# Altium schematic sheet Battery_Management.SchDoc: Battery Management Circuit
size A4; DrawnBy: Satya Mehta; Organization: Team- Ashwathama; Address1: Colorado Boulder; Address2: Author- Satya Mehta; Address3: Self Checkout Shopping Cart; DocumentNumber: 1; Revision: 1.0; SheetNumber: 1; SheetTotal: 7
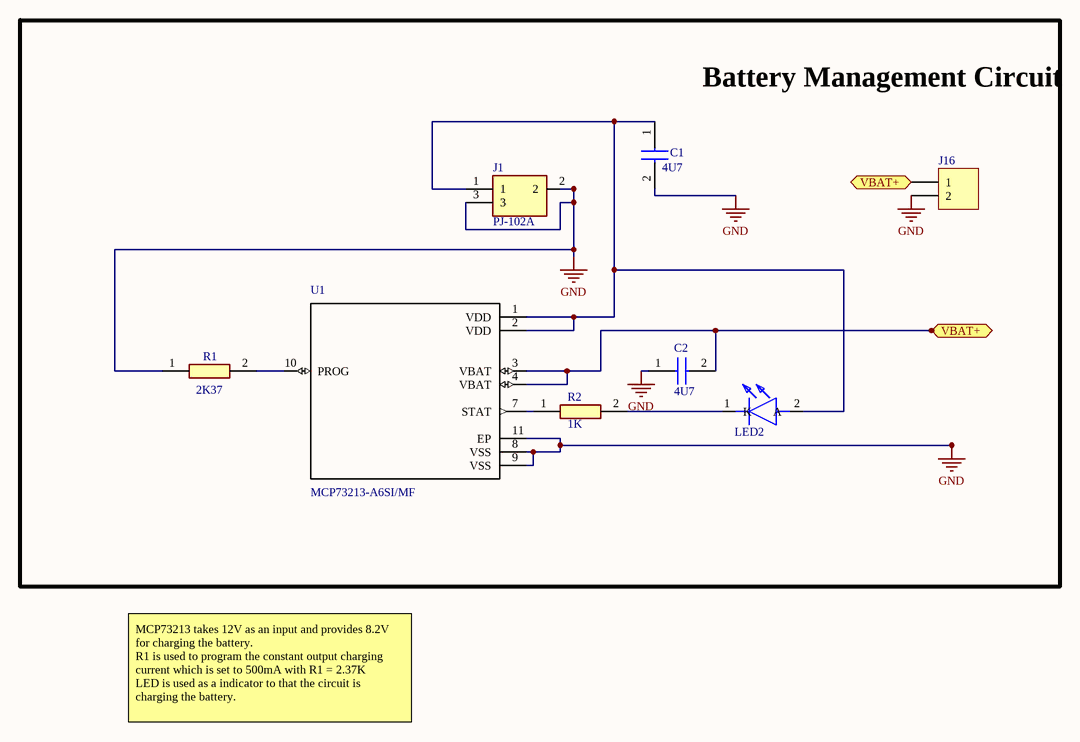
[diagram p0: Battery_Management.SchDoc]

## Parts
C1  value 4U7  [CAPC1608X90N]  (hidden comment: GRM188R61E475KE11D)
C2  value 4U7  [CAPC1608X90N]  (hidden comment: GRM188R61E475KE11D)
J1  PJ-102A  [PJ-102AH]
J16  Header 2  [HDR1X2]  (value not drawn)
LED2  SML-D12U1WT86  [LEDC1608X65N]  (value not drawn)
R1  value 2K37  [RESC1608X55N]  (hidden comment: ERJ-3EKF2371V)
R2  value 1K  [RESC1608X55N]  (hidden comment: RC0603FR-071KL)
U1  MCP73213-A6SI/MF  [*SON50P300X300X100-11N]

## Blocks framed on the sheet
Battery Management Circuit: C1 C2 J1 J16 LED2 R1 R2 U1

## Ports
VBAT+

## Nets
GND: C1.2 C2.1 J1.2 J1.3 J16.2 R1.1 U1.8(VSS) U1.9(VSS) U1.11(EP)
VBAT+: C2.2 J16.1 U1.3(VBAT) U1.4(VBAT) ; port VBAT+
NetC1_1: C1.1 J1.1 LED2.2(A) U1.1(VDD) U1.2(VDD)
NetLED2_1: LED2.1(K) R2.2
NetR1_2: R1.2 U1.10(PROG)
NetR2_1: R2.1 U1.7(STAT)

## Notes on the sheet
- MCP73213 takes 12V as an input and provides 8.2V for charging the battery.
  R1 is used to program the constant output charging current which is set to 500mA with R1 = 2.37K
  LED is used as a indicator to that the circuit is charging the battery.

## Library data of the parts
C1 C2 = GRM188R61E475KE11D: Capacitor; Manufacturer_Name: Murata Electronics
J1 = PJ-102A: Connector; Manufacturer_Name: CUI
J16 = Header 2: Header, 2-Pin; Manufacturer_Part_Number: BG301-04-A-0540-L-B; Manufacturer_Name: Global Connector Technology
LED2 = SML-D12U1WT86: LED; Manufacturer_Name: ROHM Semiconductor
R1 = ERJ-3EKF2371V: Resistor; Manufacturer_Name: Panasonic; Allied_Number: 70265728
R2 = RC0603FR-071KL: Resistor; Manufacturer_Name: YAGEO (PHYCOMP)
U1 = MCP73213-A6SI/MF: MCP Series 16V Dual-Cell Li-Ion/Li-Polymer Battery Charge Management Controller; Manufacturer_Name: Microchip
